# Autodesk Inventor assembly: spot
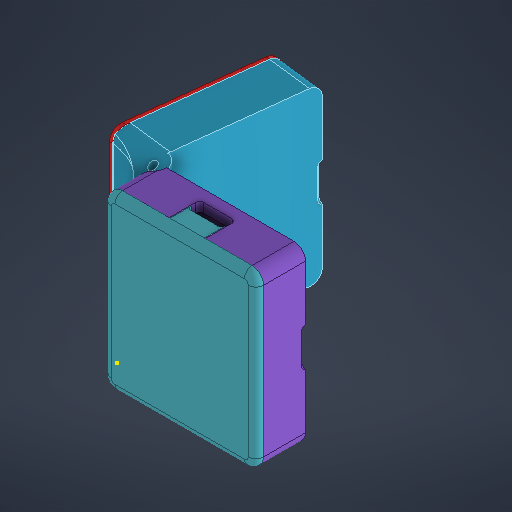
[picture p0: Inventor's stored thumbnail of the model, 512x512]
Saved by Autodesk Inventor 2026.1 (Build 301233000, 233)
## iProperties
Created: 2025-11
Part Number: spot
Document SubType Name: Assembly
Designer: Gek
Author: Gek
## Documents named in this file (5)
- F:\PROJECTS\Inventor\Workspace\SPOT\spot.iam
- F:\PROJECTS\Inventor\Workspace\SPOT\spot_CMU.ipt
- F:\PROJECTS\Inventor\Workspace\SPOT\spot_OLED.ipt
- F:\PROJECTS\Inventor\Workspace\SPOT\spot_CMU_tappo.ipt
- F:\PROJECTS\Inventor\Workspace\SPOT\spot_OLED_tappo.ipt
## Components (4 placed, 4 different names)
1. spot_CMU:1 — Coincidente:1, Coincidente:2, Inserimento:1
2. spot_OLED:1 — Coincidente:3, Coincidente:4, Inserimento:1
3. spot_CMU_tappo:1 — Coincidente:1, Coincidente:2
4. spot_OLED_tappo:1 — Coincidente:3, Coincidente:4
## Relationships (5: Mate 4, Insert 1)
- Coincidente:1 [Mate]: spot_CMU:1 ↔ spot_CMU_tappo:1
- Coincidente:2 [Mate]: spot_CMU:1 ↔ spot_CMU_tappo:1
- Coincidente:3 [Mate]: spot_OLED:1 ↔ spot_OLED_tappo:1
- Coincidente:4 [Mate]: spot_OLED:1 ↔ spot_OLED_tappo:1
- Inserimento:1: spot_CMU:1 ↔ spot_OLED:1
